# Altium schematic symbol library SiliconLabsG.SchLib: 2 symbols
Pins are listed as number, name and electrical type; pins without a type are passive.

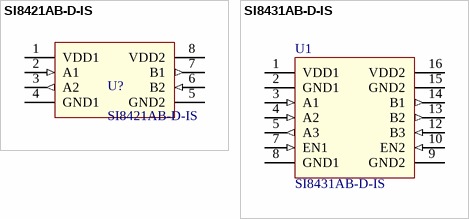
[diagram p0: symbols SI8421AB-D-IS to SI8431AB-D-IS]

## SI8421AB-D-IS
designator U?
Digital Isolator 2ch
footprint SOIC127P600-8N (SOIC, 8-Leads, Body 4.9x3.9mm, Pitch 1.27mm, IPC Medium Density)
pins: 1 VDD1 (power), 2 A1 (in), 3 A2 (out), 4 GND1 (power), 5 GND2 (power), 6 B2 (in), 7 B1 (out), 8 VDD2 (power)

## SI8431AB-D-IS
designator U1
3 channel Isolator
footprint SOIC127P1030-16N (SOIC, 16-Leads, Body 10.3x7.5mm, Pitch 1.27mm, IPC Medium Density)
pins: 1 VDD1 (power), 2 GND1 (power), 3 A1 (in), 4 A2 (in), 5 A3 (out), 7 EN1 (in), 8 GND1 (power), 9 GND2 (power), 10 EN2 (in), 12 B3 (in), 13 B2 (out), 14 B1 (out), 15 GND2 (power), 16 VDD2 (power)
